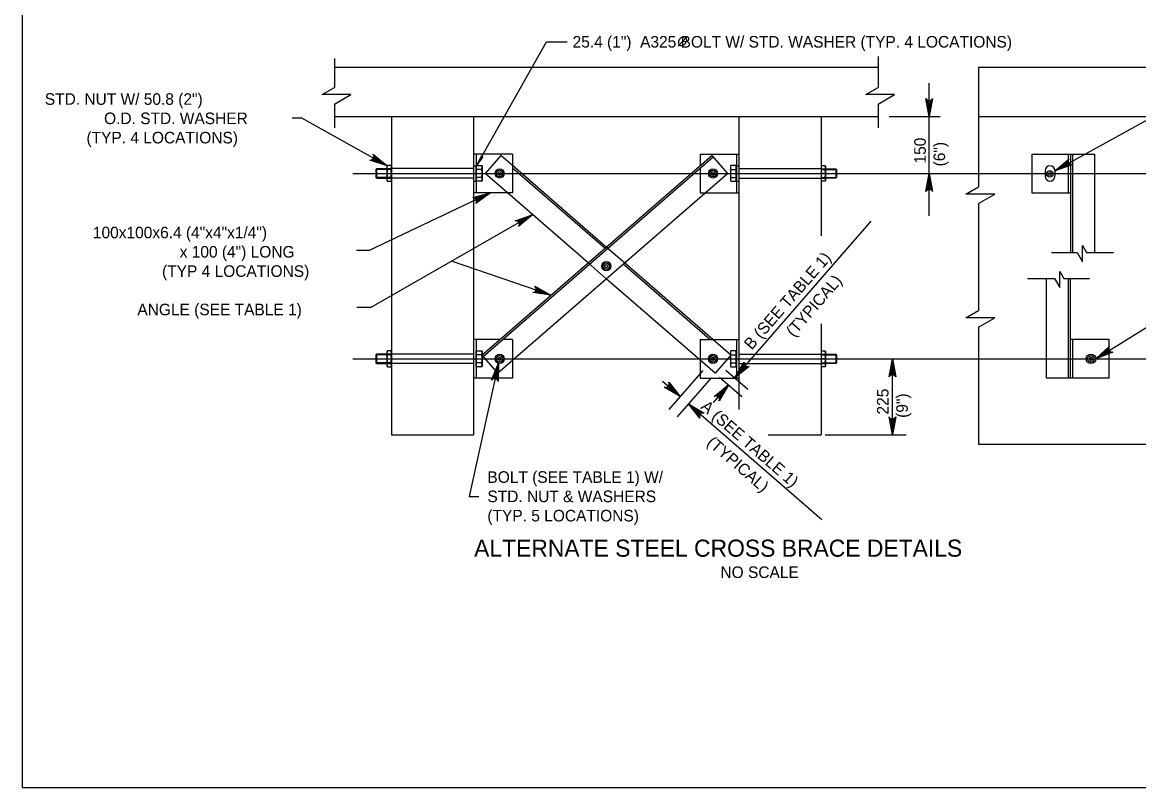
# Model space of a CAD drawing. Extents: x 638263 to 640360, y 293683 to 298655.
# Drawn here: x 639316.5 to 639605.5, y 297856.5 to 298054.8 of the extents above; entities that cross this region are included whole.
import ezdxf

# ---------------------------------------------------------------- set-up
doc = ezdxf.new("R2010")
doc.units = 0
for name, color, linetype in [('2', 7, 'Continuous'), ('3', 7, 'Continuous'), ('4', 7, 'Continuous'), ('5', 7, 'Continuous'), ('8', 7, 'Continuous')]:
    doc.layers.add(name, color=color, linetype=linetype)

msp = doc.modelspace()

# ---------------------------------------------------------------- linework, layer by layer
at = {"layer": '2'}
for p, q in [((639316.46, 297856.46), (639316.46, 298420.46)), ((640102.46, 297856.46), (639316.46, 297856.46))]:
    msp.add_line(p, q, dxfattribs=at)
at = {"layer": '3'}
for p, q in [((639452.21, 298049.71), (639457.53, 298049.71)), ((639551.3, 298004.61), (639551.3, 298038.95)), ((639491.93, 298010.58), (639493.26, 298010.58)), ((639493.26, 298010.58), (639502.01, 298010.58)), ((639541.75, 297947.88), (639541.75, 297967.57))]:
    msp.add_line(p, q, dxfattribs=at)
for points in [[(639434.01, 298017.37), (639452.21, 298049.71)], [(639551.3, 298030.36), (639550.43, 298035.02), (639550.67, 298034.67), (639550.99, 298034.48), (639551.3, 298034.43), (639551.61, 298034.48), (639551.92, 298034.67), (639552.17, 298035.02), (639551.3, 298030.36), (639551.92, 298034.67), (639551.61, 298034.48), (639551.3, 298030.36), (639551.3, 298034.43), (639550.99, 298034.48), (639551.3, 298030.36), (639550.67, 298034.67)], [(639583.78, 298016.32), (639615.38, 298033.76), (639618.6, 298033.76)], [(639551.3, 298015.6), (639552.17, 298010.94), (639551.92, 298011.3), (639551.61, 298011.48), (639551.3, 298011.54), (639550.99, 298011.48), (639550.67, 298011.3), (639550.42, 298010.94), (639551.3, 298015.6), (639550.67, 298011.3), (639550.99, 298011.48), (639551.3, 298015.6), (639551.3, 298011.54), (639551.61, 298011.48), (639551.3, 298015.6), (639551.92, 298011.3)], [(639448.57, 298004.92), (639444.96, 298001.84), (639445.15, 298002.24), (639445.15, 298002.6), (639445.05, 298002.9), (639444.84, 298003.14), (639444.53, 298003.32), (639444.09, 298003.36), (639448.57, 298004.92), (639444.53, 298003.32), (639444.84, 298003.14), (639448.57, 298004.92), (639445.05, 298002.9), (639445.15, 298002.6), (639448.57, 298004.92), (639445.15, 298002.24)], [(639453.31, 297984.07), (639427.55, 297992.84)], [(639453.31, 297984.07), (639448.62, 297984.74), (639449.04, 297984.86), (639449.31, 297985.1), (639449.46, 297985.38), (639449.51, 297985.69), (639449.44, 297986.04), (639449.18, 297986.4), (639453.31, 297984.07), (639449.44, 297986.04), (639449.51, 297985.69), (639453.31, 297984.07), (639449.46, 297985.38), (639449.31, 297985.1), (639453.31, 297984.07), (639449.04, 297984.86)], [(639594.41, 297967.57), (639614.98, 297980.35), (639618.6, 297980.35)], [(639439.78, 297966.42), (639432.16, 297931.94), (639434.62, 297931.94)], [(639439.78, 297966.42), (639439.63, 297961.68), (639439.46, 297962.08), (639439.2, 297962.33), (639438.9, 297962.45), (639438.59, 297962.46), (639438.24, 297962.35), (639437.92, 297962.05), (639439.78, 297966.42), (639438.24, 297962.35), (639438.59, 297962.46), (639439.78, 297966.42), (639438.9, 297962.45), (639439.2, 297962.33), (639439.78, 297966.42), (639439.46, 297962.08)]]:
    msp.add_lwpolyline(points, dxfattribs=at)
msp.add_lwpolyline([(639434.01, 298017.37), (639435.7, 298019.86), (639435.26, 298020.11)], close=True, dxfattribs=at)
at = {"layer": '4'}
msp.add_line((639486.25, 298048.54), (639488.49, 298050.99), dxfattribs=at)
msp.add_spline([(639488.26, 298050.75), (639488.08, 298050.88), (639487.91, 298050.93), (639487.69, 298050.95), (639487.56, 298050.95), (639487.35, 298050.9), (639487.15, 298050.81), (639487.01, 298050.73), (639486.75, 298050.52), (639486.54, 298050.25), (639486.41, 298050), (639486.34, 298049.77), (639486.32, 298049.55), (639486.34, 298049.37), (639486.43, 298049.1), (639486.53, 298048.97), (639486.72, 298048.82), (639487.01, 298048.75), (639487.34, 298048.76), (639487.76, 298048.95), (639488.06, 298049.21), (639488.29, 298049.53), (639488.44, 298049.86), (639488.49, 298050.23), (639488.43, 298050.47), (639488.27, 298050.75)], degree=3, dxfattribs=at)
at = {"layer": '5'}
for p, q in [((639397.28, 298045.41), (639397.28, 298037.88)), ((639538.03, 298045.93), (639538.03, 298037.88)), ((639397.28, 298043.16), (639538.03, 298043.16)), ((639564, 298043.16), (639564, 298012.11)), ((639564, 298043.16), (639610.39, 298043.16)), ((639394.08, 298036.03), (639397.28, 298037.88)), ((639401.55, 298036.03), (639394.08, 298036.03)), ((639397.28, 298033.57), (639401.55, 298036.03)), ((639534.83, 298036.03), (639538.03, 298037.88)), ((639542.29, 298036.03), (639534.83, 298036.03)), ((639538.03, 298033.57), (639542.29, 298036.03)), ((639397.28, 298033.57), (639397.28, 298027.46)), ((639538.03, 298033.57), (639538.03, 298027.46)), ((639397.28, 298030.36), (639538.03, 298030.36)), ((639412.05, 298030.36), (639412.05, 297947.88)), ((639433.31, 298030.36), (639433.31, 297947.88)), ((639502.01, 298030.36), (639502.01, 297954.44)), ((639523.27, 298030.36), (639523.27, 297999.44)), ((639564, 298030.36), (639610.39, 298030.36)), ((639433.31, 298020.62), (639433.31, 298010.58)), ((639443.38, 298020.62), (639433.31, 298020.62)), ((639433.93, 298020.62), (639433.93, 298010.58)), ((639435.43, 297968.52), (639494.98, 298020.29)), ((639435.75, 297968.15), (639495.3, 298019.92)), ((639440.34, 298020.29), (639436.27, 298015.62)), ((639443.38, 298017.65), (639440.34, 298020.29)), ((639443.38, 298020.62), (639443.38, 298010.58)), ((639491.93, 298020.62), (639491.93, 298017.65)), ((639491.93, 298020.62), (639502.01, 298020.62)), ((639494.98, 298020.29), (639499.05, 298015.62)), ((639501.38, 298020.62), (639501.38, 298010.58)), ((639502.01, 298020.62), (639502.01, 298010.58)), ((639577.81, 298020.62), (639594.05, 298020.62)), ((639577.81, 298020.62), (639577.81, 298010.58)), ((639587.26, 298020.62), (639587.26, 298010.58)), ((639587.85, 298020.62), (639587.85, 297995.15)), ((639588.34, 298020.62), (639588.34, 297995.15)), ((639594.05, 298020.62), (639594.05, 297995.15)), ((639402.01, 298015.6), (639533.31, 298015.6)), ((639408.17, 298016.78), (639408.01, 298016.62)), ((639408.01, 298016.62), (639408.01, 298014.58)), ((639408.17, 298016.78), (639408.17, 298014.42)), ((639412.05, 298016.78), (639408.17, 298016.78)), ((639412.05, 298016.62), (639408.17, 298016.62)), ((639410.72, 298015.6), (639412.2, 298015.6)), ((639411.02, 298017.65), (639410.87, 298017.38)), ((639410.87, 298017.38), (639410.87, 298013.83)), ((639412.05, 298016.78), (639410.87, 298016.78)), ((639411.89, 298017.65), (639411.02, 298017.65)), ((639411.89, 298016.62), (639411.02, 298016.62)), ((639411.89, 298017.65), (639412.05, 298017.38)), ((639412.05, 298017.38), (639412.05, 298013.83)), ((639433.31, 298016.85), (639412.05, 298016.85)), ((639412.05, 298016.78), (639412.05, 298014.42)), ((639433.31, 298017.57), (639433.93, 298017.57)), ((639433.93, 298016.78), (639433.88, 298016.78)), ((639433.93, 298017.37), (639433.93, 298013.83)), ((639434.01, 298017.37), (639433.93, 298017.37)), ((639434.01, 298013.56), (639434.01, 298017.65)), ((639434.01, 298017.65), (639435.37, 298017.65)), ((639435.37, 298016.62), (639434.01, 298016.62)), ((639435.37, 298017.65), (639435.53, 298017.38)), ((639435.53, 298017.38), (639435.53, 298013.83)), ((639442.06, 298010.58), (639436.27, 298015.62)), ((639439.5, 297963.84), (639499.05, 298015.62)), ((639467.66, 297996.54), (639443.38, 298017.65)), ((639467.34, 297996.17), (639443.38, 298016.99)), ((639491.93, 298016.99), (639491.93, 298010.58)), ((639499.94, 298017.65), (639499.79, 298017.38)), ((639499.79, 298017.38), (639499.79, 298013.83)), ((639501.3, 298017.65), (639499.94, 298017.65)), ((639499.94, 298016.62), (639501.3, 298016.62)), ((639501.3, 298013.56), (639501.3, 298017.65)), ((639501.3, 298017.37), (639501.38, 298017.37)), ((639501.38, 298017.57), (639502.01, 298017.57)), ((639501.38, 298017.37), (639501.38, 298013.83)), ((639501.38, 298016.78), (639501.43, 298016.78)), ((639502.01, 298016.85), (639523.27, 298016.85)), ((639524.6, 298015.6), (639523.12, 298015.6)), ((639523.42, 298017.65), (639523.27, 298017.38)), ((639523.27, 298017.38), (639523.27, 298013.83)), ((639523.27, 298016.78), (639523.27, 298014.42)), ((639523.27, 298016.78), (639524.45, 298016.78)), ((639523.27, 298016.78), (639527.14, 298016.78)), ((639523.27, 298016.62), (639527.14, 298016.62)), ((639523.42, 298017.65), (639524.29, 298017.65)), ((639523.42, 298016.62), (639524.29, 298016.62)), ((639524.29, 298017.65), (639524.45, 298017.38)), ((639524.45, 298017.38), (639524.45, 298013.83)), ((639527.14, 298016.78), (639527.14, 298014.42)), ((639527.14, 298016.78), (639527.3, 298016.62)), ((639527.3, 298016.62), (639527.3, 298014.58)), ((639533.31, 298015.6), (639617.26, 298015.6)), ((639581.28, 298016.32), (639581.28, 298014.88)), ((639583.78, 298016.32), (639583.78, 298014.88)), ((639408.01, 298014.58), (639408.17, 298014.42)), ((639412.05, 298014.58), (639408.17, 298014.58)), ((639408.17, 298014.42), (639412.05, 298014.42)), ((639412.05, 298014.42), (639410.87, 298014.42)), ((639410.87, 298013.83), (639411.02, 298013.56)), ((639411.89, 298014.58), (639411.02, 298014.58)), ((639411.02, 298013.56), (639411.89, 298013.56)), ((639412.05, 298013.83), (639411.89, 298013.56)), ((639433.31, 298014.35), (639412.05, 298014.35)), ((639433.31, 298013.63), (639433.93, 298013.63)), ((639433.93, 298014.42), (639433.88, 298014.42)), ((639435.37, 298014.58), (639434.01, 298014.58)), ((639435.37, 298013.56), (639434.01, 298013.56)), ((639435.53, 298013.83), (639435.37, 298013.56)), ((639499.79, 298013.83), (639499.94, 298013.56)), ((639499.94, 298014.58), (639501.3, 298014.58)), ((639499.94, 298013.56), (639501.3, 298013.56)), ((639501.38, 298014.42), (639501.43, 298014.42)), ((639501.38, 298013.63), (639502.01, 298013.63)), ((639502.01, 298014.35), (639523.27, 298014.35)), ((639523.27, 298014.58), (639527.14, 298014.58)), ((639523.27, 298014.42), (639524.45, 298014.42)), ((639527.14, 298014.42), (639523.27, 298014.42)), ((639523.27, 298013.83), (639523.42, 298013.56)), ((639523.42, 298014.58), (639524.29, 298014.58)), ((639524.29, 298013.56), (639523.42, 298013.56)), ((639524.45, 298013.83), (639524.29, 298013.56)), ((639527.3, 298014.58), (639527.14, 298014.42)), ((639443.38, 298010.58), (639433.31, 298010.58)), ((639462.93, 297992.43), (639442.06, 298010.58)), ((639560.8, 298010.27), (639564, 298012.11)), ((639568.26, 298010.27), (639560.8, 298010.27)), ((639564, 298007.8), (639568.26, 298010.27)), ((639577.81, 298010.58), (639587.85, 298010.58)), ((639564, 298007.8), (639564, 297980.06)), ((639472.38, 297992.43), (639467.66, 297996.54)), ((639582.93, 297995.15), (639589.55, 297995.15)), ((639589.55, 297995.15), (639590.94, 297992.74)), ((639590.94, 297992.74), (639590.94, 297996.95)), ((639590.94, 297996.95), (639591.98, 297995.15)), ((639591.98, 297995.15), (639598.97, 297995.15)), ((639467.66, 297988.32), (639462.93, 297992.43)), ((639494.46, 297972.59), (639472.06, 297992.06)), ((639495.21, 297972.59), (639472.38, 297992.43)), ((639585.12, 297990.23), (639586.16, 297988.42)), ((639585.12, 297986.02), (639585.12, 297990.23)), ((639491.93, 297967.22), (639467.66, 297988.32)), ((639576.73, 297988.42), (639583.73, 297988.42)), ((639581.65, 297962.55), (639581.65, 297988.42)), ((639583.73, 297988.42), (639585.12, 297986.02)), ((639586.16, 297988.42), (639592.77, 297988.42)), ((639587.36, 297962.55), (639587.36, 297988.42)), ((639587.85, 297962.55), (639587.85, 297988.42)), ((639560.8, 297978.21), (639564, 297980.06)), ((639568.26, 297978.21), (639560.8, 297978.21)), ((639564, 297975.75), (639568.26, 297978.21)), ((639523.27, 297976.62), (639523.27, 297947.88)), ((639564, 297975.75), (639564, 297945.42)), ((639433.31, 297972.59), (639433.31, 297962.55)), ((639440.11, 297972.59), (639433.31, 297972.59)), ((639433.93, 297972.59), (639433.93, 297962.55)), ((639443.38, 297972.59), (639440.86, 297972.59)), ((639443.38, 297972.59), (639443.38, 297967.22)), ((639491.93, 297972.59), (639491.93, 297962.55)), ((639491.93, 297972.59), (639502.01, 297972.59)), ((639499.89, 297968.52), (639495.21, 297972.59)), ((639501.38, 297972.59), (639501.38, 297962.55)), ((639502.01, 297972.59), (639502.01, 297962.55)), ((639597.89, 297972.59), (639587.85, 297972.59)), ((639588.44, 297962.55), (639588.44, 297972.59)), ((639597.89, 297962.55), (639597.89, 297972.59)), ((639411.02, 297969.62), (639410.87, 297969.34)), ((639410.87, 297969.34), (639410.87, 297965.79)), ((639411.89, 297969.62), (639411.02, 297969.62)), ((639411.89, 297969.62), (639412.05, 297969.34)), ((639412.05, 297969.34), (639412.05, 297965.79)), ((639433.93, 297969.34), (639433.93, 297965.8)), ((639434.01, 297969.34), (639433.93, 297969.34)), ((639434.01, 297965.52), (639434.01, 297969.62)), ((639434.01, 297969.62), (639435.37, 297969.62)), ((639435.37, 297969.62), (639435.53, 297969.34)), ((639435.53, 297969.34), (639435.53, 297965.79)), ((639499.94, 297969.62), (639499.79, 297969.34)), ((639499.79, 297969.34), (639499.79, 297965.79)), ((639501.3, 297969.62), (639499.94, 297969.62)), ((639501.3, 297965.52), (639501.3, 297969.62)), ((639501.3, 297969.34), (639501.38, 297969.34)), ((639501.38, 297969.34), (639501.38, 297965.8)), ((639523.42, 297969.62), (639523.27, 297969.34)), ((639523.27, 297969.34), (639523.27, 297965.79)), ((639523.42, 297969.62), (639524.29, 297969.62)), ((639524.29, 297969.62), (639524.45, 297969.34)), ((639524.45, 297969.34), (639524.45, 297965.79)), ((639402.01, 297967.57), (639533.31, 297967.57)), ((639408.17, 297968.75), (639408.01, 297968.59)), ((639408.01, 297968.59), (639408.01, 297966.55)), ((639408.01, 297966.55), (639408.17, 297966.39)), ((639412.05, 297968.75), (639408.17, 297968.75)), ((639408.17, 297968.75), (639408.17, 297966.39)), ((639412.05, 297968.59), (639408.17, 297968.59)), ((639412.05, 297966.55), (639408.17, 297966.55)), ((639408.17, 297966.39), (639412.05, 297966.39)), ((639410.72, 297967.57), (639412.2, 297967.57)), ((639412.05, 297968.75), (639410.87, 297968.75)), ((639412.05, 297966.39), (639410.87, 297966.39)), ((639411.89, 297968.59), (639411.02, 297968.59)), ((639411.89, 297966.55), (639411.02, 297966.55)), ((639433.31, 297968.82), (639412.05, 297968.82)), ((639412.05, 297968.75), (639412.05, 297966.39)), ((639433.31, 297966.32), (639412.05, 297966.32)), ((639433.93, 297968.75), (639433.88, 297968.75)), ((639433.93, 297966.39), (639433.88, 297966.39)), ((639435.37, 297968.59), (639434.01, 297968.59)), ((639435.37, 297966.55), (639434.01, 297966.55)), ((639435.43, 297968.52), (639439.5, 297963.84)), ((639443.38, 297967.22), (639443.38, 297962.55)), ((639495.82, 297963.84), (639491.93, 297967.22)), ((639499.89, 297968.52), (639495.82, 297963.84)), ((639499.94, 297968.59), (639501.3, 297968.59)), ((639499.94, 297966.55), (639501.3, 297966.55)), ((639501.38, 297968.75), (639501.43, 297968.75)), ((639501.38, 297966.39), (639501.43, 297966.39)), ((639502.01, 297968.82), (639523.27, 297968.82)), ((639502.01, 297966.32), (639523.27, 297966.32)), ((639524.6, 297967.57), (639523.12, 297967.57)), ((639523.27, 297968.75), (639523.27, 297966.39)), ((639523.27, 297968.75), (639524.45, 297968.75)), ((639523.27, 297968.75), (639527.14, 297968.75)), ((639523.27, 297968.59), (639527.14, 297968.59)), ((639523.27, 297966.55), (639527.14, 297966.55)), ((639523.27, 297966.39), (639524.45, 297966.39)), ((639527.14, 297966.39), (639523.27, 297966.39)), ((639523.42, 297968.59), (639524.29, 297968.59)), ((639523.42, 297966.55), (639524.29, 297966.55)), ((639527.14, 297968.75), (639527.14, 297966.39)), ((639527.14, 297968.75), (639527.3, 297968.59)), ((639527.3, 297966.55), (639527.14, 297966.39)), ((639527.3, 297968.59), (639527.3, 297966.55)), ((639533.31, 297967.57), (639617.26, 297967.57)), ((639410.87, 297965.79), (639411.02, 297965.52)), ((639411.02, 297965.52), (639411.89, 297965.52)), ((639412.05, 297965.79), (639411.89, 297965.52)), ((639435.37, 297965.52), (639434.01, 297965.52)), ((639435.53, 297965.79), (639435.37, 297965.52)), ((639499.79, 297965.79), (639499.94, 297965.52)), ((639499.94, 297965.52), (639501.3, 297965.52)), ((639523.27, 297965.79), (639523.42, 297965.52)), ((639524.29, 297965.52), (639523.42, 297965.52)), ((639524.45, 297965.79), (639524.29, 297965.52)), ((639443.38, 297962.55), (639433.31, 297962.55)), ((639491.93, 297962.55), (639502.01, 297962.55)), ((639597.89, 297962.55), (639581.65, 297962.55)), ((639412.05, 297947.88), (639433.31, 297947.88)), ((639509.55, 297947.88), (639523.27, 297947.88)), ((639564, 297945.42), (639610.39, 297945.42))]:
    msp.add_line(p, q, dxfattribs=at)
for points in [[(639410.96, 298017.54), (639388.84, 298029.88), (639386.35, 298029.88)], [(639410.96, 298017.54), (639406.46, 298019.04), (639406.9, 298019.09), (639407.21, 298019.27), (639407.41, 298019.52), (639407.52, 298019.82), (639407.51, 298020.18), (639407.31, 298020.57), (639410.96, 298017.54), (639407.51, 298020.18), (639407.52, 298019.82), (639410.96, 298017.54), (639407.41, 298019.52), (639407.21, 298019.27), (639410.96, 298017.54), (639406.9, 298019.09)], [(639437.68, 298010.58), (639406.26, 297995.64), (639402.95, 297995.64)], [(639437.68, 298010.58), (639433.85, 298007.79), (639434.06, 298008.17), (639434.1, 298008.53), (639434.01, 298008.84), (639433.83, 298009.09), (639433.53, 298009.3), (639433.1, 298009.37), (639437.68, 298010.58), (639433.53, 298009.3), (639433.83, 298009.09), (639437.68, 298010.58), (639434.01, 298008.84), (639434.1, 298008.53), (639437.68, 298010.58), (639434.06, 298008.17)], [(639448.57, 298004.92), (639406.69, 297980.84), (639403.1, 297980.84)]]:
    msp.add_lwpolyline(points, dxfattribs=at)
for centre, radius in [((639440.04, 298015.6), 1.18), ((639440.04, 298015.6), 0.833), ((639440.04, 298015.6), 0.417), ((639495.28, 298015.6), 1.18), ((639495.28, 298015.6), 0.833), ((639495.28, 298015.6), 0.417), ((639582.5, 298015.47), 0.833), ((639582.5, 298015.47), 0.417), ((639467.66, 297991.58), 1.18), ((639467.66, 297991.58), 0.833), ((639467.66, 297991.58), 0.417), ((639440.04, 297967.57), 1.18), ((639440.04, 297967.57), 0.833), ((639440.04, 297967.57), 0.417), ((639495.28, 297967.57), 1.18), ((639495.28, 297967.57), 0.833), ((639495.28, 297967.57), 0.417), ((639593.16, 297967.57), 1.25), ((639593.16, 297967.57), 0.833), ((639593.16, 297967.57), 0.417)]:
    msp.add_circle(centre, radius, dxfattribs=at)
for centre, radius, start, end in [((639411.78, 298017.13), 0.915, 146, 214), ((639414.29, 298015.6), 3.42, 162.6175, 197.3825), ((639411.13, 298017.13), 0.915, 326, 34), ((639408.62, 298015.6), 3.42, 342.6175, 17.3825), ((639434.62, 298017.13), 0.915, 326, 34), ((639432.11, 298015.6), 3.42, 342.6175, 17.3825), ((639500.7, 298017.13), 0.915, 146, 214), ((639503.21, 298015.6), 3.42, 162.6175, 197.3825), ((639524.18, 298017.13), 0.915, 146, 214), ((639526.69, 298015.6), 3.42, 162.6175, 197.3825), ((639523.54, 298017.13), 0.915, 326, 34), ((639521.03, 298015.6), 3.42, 342.6175, 17.3825), ((639582.54, 298016.32), 1.25, 0, 180), ((639411.78, 298014.07), 0.915, 146, 214), ((639411.13, 298014.07), 0.915, 326, 34), ((639434.62, 298014.07), 0.915, 326, 34), ((639500.7, 298014.07), 0.915, 146, 214), ((639524.18, 298014.07), 0.915, 146, 214), ((639523.54, 298014.07), 0.915, 326, 34), ((639582.54, 298014.88), 1.25, 180, 0), ((639411.78, 297969.1), 0.915, 146, 214), ((639411.13, 297969.1), 0.915, 326, 34), ((639434.62, 297969.1), 0.915, 326, 34), ((639500.7, 297969.1), 0.915, 146, 214), ((639524.18, 297969.1), 0.915, 146, 214), ((639523.54, 297969.1), 0.915, 326, 34), ((639414.29, 297967.57), 3.42, 162.6175, 197.3825), ((639411.78, 297966.03), 0.915, 146, 214), ((639408.62, 297967.57), 3.42, 342.6175, 17.3825), ((639411.13, 297966.03), 0.915, 326, 34), ((639432.11, 297967.57), 3.42, 342.6175, 17.3825), ((639434.62, 297966.03), 0.915, 326, 34), ((639503.21, 297967.57), 3.42, 162.6175, 197.3825), ((639500.7, 297966.03), 0.915, 146, 214), ((639526.69, 297967.57), 3.42, 162.6175, 197.3825), ((639524.18, 297966.03), 0.915, 146, 214), ((639521.03, 297967.57), 3.42, 342.6175, 17.3825), ((639523.54, 297966.03), 0.915, 326, 34)]:
    msp.add_arc(centre, radius, start, end, dxfattribs=at)
at = {"layer": '8'}
for p, q in [((639540.93, 298030.36), (639554.09, 298030.36)), ((639539.59, 298015.6), (639553.44, 298015.6)), ((639500.94, 297962.66), (639536.25, 298003.27)), ((639524.83, 297967.57), (639542.74, 297967.57)), ((639492.64, 297964.53), (639483.83, 297954.4)), ((639498.61, 297964.67), (639504.33, 297959.7)), ((639486.78, 297957.79), (639482.25, 297961.73)), ((639494.8, 297962.66), (639485.98, 297952.52)), ((639499.32, 297960.8), (639495.38, 297956.27)), ((639497, 297962.81), (639502.72, 297957.84)), ((639488.94, 297955.92), (639523.44, 297925.92)), ((639524.33, 297947.88), (639545.27, 297947.88))]:
    msp.add_line(p, q, dxfattribs=at)
for points in [[(639583.78, 298016.32), (639587.44, 298019.34), (639587.25, 298018.94), (639587.24, 298018.58), (639587.34, 298018.28), (639587.54, 298018.03), (639587.85, 298017.85), (639588.29, 298017.81), (639583.78, 298016.32), (639587.85, 298017.85), (639587.54, 298018.03), (639583.78, 298016.32), (639587.34, 298018.28), (639587.24, 298018.58), (639583.78, 298016.32), (639587.25, 298018.94)], [(639594.41, 297967.57), (639597.91, 297970.77), (639597.74, 297970.37), (639597.75, 297970.01), (639597.86, 297969.71), (639598.08, 297969.48), (639598.4, 297969.31), (639598.83, 297969.29), (639594.41, 297967.57), (639598.4, 297969.31), (639598.08, 297969.48), (639594.41, 297967.57), (639597.86, 297969.71), (639597.75, 297970.01), (639594.41, 297967.57), (639597.74, 297970.37)], [(639500.94, 297962.66), (639503.33, 297966.74), (639503.29, 297966.31), (639503.4, 297965.97), (639503.6, 297965.72), (639503.87, 297965.56), (639504.23, 297965.49), (639504.65, 297965.6), (639500.94, 297962.66), (639504.23, 297965.49), (639503.87, 297965.56), (639500.94, 297962.66), (639503.6, 297965.72), (639503.4, 297965.97), (639500.94, 297962.66), (639503.29, 297966.31)], [(639541.75, 297967.57), (639542.62, 297962.91), (639542.37, 297963.27), (639542.06, 297963.45), (639541.75, 297963.51), (639541.43, 297963.45), (639541.12, 297963.27), (639540.87, 297962.91), (639541.75, 297967.57), (639541.12, 297963.27), (639541.43, 297963.45), (639541.75, 297967.57), (639541.75, 297963.51), (639542.06, 297963.45), (639541.75, 297967.57), (639542.37, 297963.27)], [(639486.78, 297957.79), (639482.69, 297960.19), (639483.13, 297960.14), (639483.47, 297960.26), (639483.72, 297960.46), (639483.88, 297960.73), (639483.95, 297961.09), (639483.84, 297961.51), (639486.78, 297957.79), (639483.95, 297961.09), (639483.88, 297960.73), (639486.78, 297957.79), (639483.72, 297960.46), (639483.47, 297960.26), (639486.78, 297957.79), (639483.13, 297960.14)], [(639499.32, 297960.8), (639496.92, 297956.71), (639496.97, 297957.14), (639496.86, 297957.49), (639496.66, 297957.73), (639496.39, 297957.89), (639496.03, 297957.96), (639495.6, 297957.85), (639499.32, 297960.8), (639496.03, 297957.96), (639496.39, 297957.89), (639499.32, 297960.8), (639496.66, 297957.73), (639496.86, 297957.49), (639499.32, 297960.8), (639496.97, 297957.14)], [(639488.94, 297955.92), (639493.03, 297953.52), (639492.59, 297953.57), (639492.25, 297953.46), (639492, 297953.26), (639491.84, 297952.98), (639491.77, 297952.63), (639491.88, 297952.21), (639488.94, 297955.92), (639491.77, 297952.63), (639491.84, 297952.98), (639488.94, 297955.92), (639492, 297953.26), (639492.25, 297953.46), (639488.94, 297955.92), (639492.59, 297953.57)], [(639541.75, 297947.88), (639540.87, 297952.54), (639541.12, 297952.19), (639541.43, 297952), (639541.75, 297951.95), (639542.06, 297952), (639542.37, 297952.19), (639542.62, 297952.54), (639541.75, 297947.88), (639542.37, 297952.19), (639542.06, 297952), (639541.75, 297947.88), (639541.75, 297951.95), (639541.43, 297952), (639541.75, 297947.88), (639541.12, 297952.19)]]:
    msp.add_lwpolyline(points, dxfattribs=at)

# ---------------------------------------------------------------- texts
at = {"layer": '3'}
for s, height, p in [('25.4 (1")  A325 BOLT W/ STD. WASHER (TYP. 4 LOCATIONS)', 3, (639458.94, 298048.21)), (' STD. NUT W/ 50.8 (2")', 3, (639321.16, 298033.38)), ('O.D. STD. WASHER', 3, (639337.62, 298028.38)), ('(TYP. 4 LOCATIONS)', 3, (639333.06, 298023.38)), ('100x100x6.4 (4"x4"x1/4")', 3, (639334.73, 297998.8)), ('x 100 (4") LONG', 3, (639357.2, 297993.8)), ('(TYP 4 LOCATIONS)', 3, (639352.64, 297988.8)), ('ANGLE (SEE TABLE 1)', 3, (639346.24, 297978.85)), ('BOLT (SEE TABLE 1) W/', 3, (639436.88, 297935.44)), ('STD. NUT & WASHERS', 3, (639436.88, 297930.44)), ('(TYP. 5 LOCATIONS)', 3, (639436.88, 297925.44)), ('ALTERNATE STEEL CROSS BRACE DETAILS', 4.4292, (639433.44, 297916.3)), ('NO SCALE', 3, (639497.22, 297910.78))]:
    msp.add_text(s, height=height, dxfattribs=at).set_placement(p)
for s, p in [('150', (639550.4, 298018.17)), ('(6")', (639555.4, 298017.43)), ('225', (639540.75, 297953.15)), ('(9")', (639545.75, 297952.28))]:
    msp.add_text(s, height=3, rotation=90, dxfattribs=at).set_placement(p)
at = {"layer": '8'}
for s, rotation, p in [(' B (SEE TABLE 1)', 48.9947, (639504.58, 297968.86)), ('(TYPICAL)', 48.9947, (639516.18, 297973.05)), (' A (SEE TABLE 1)', 318.996, (639491.07, 297955.57)), ('(TYPICAL)', 318.996, (639493.48, 297945.51))]:
    msp.add_text(s, height=3, rotation=rotation, dxfattribs=at).set_placement(p)

doc.saveas('drawing.dxf')
